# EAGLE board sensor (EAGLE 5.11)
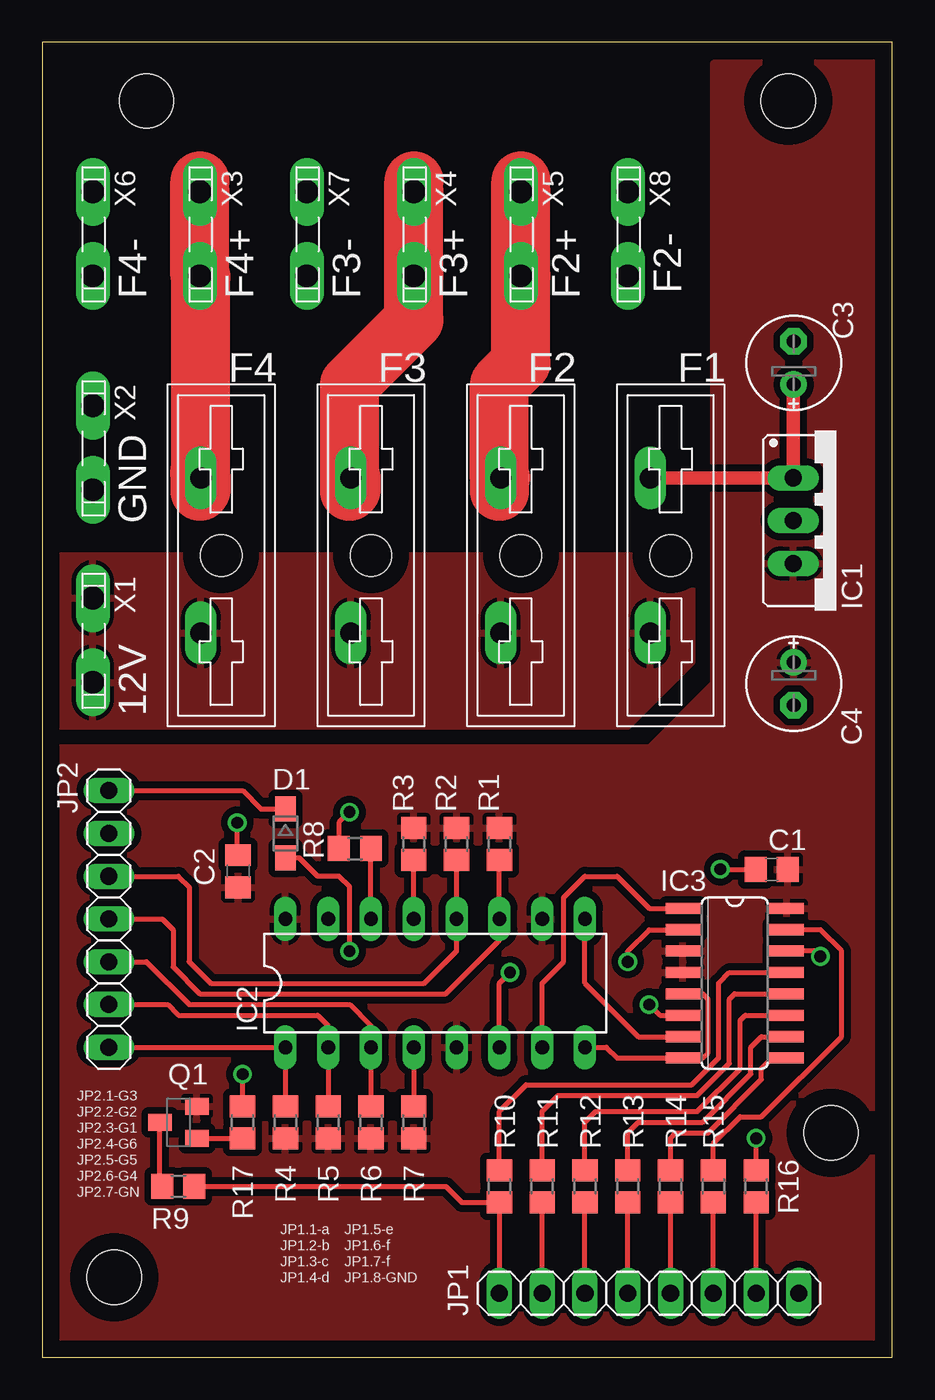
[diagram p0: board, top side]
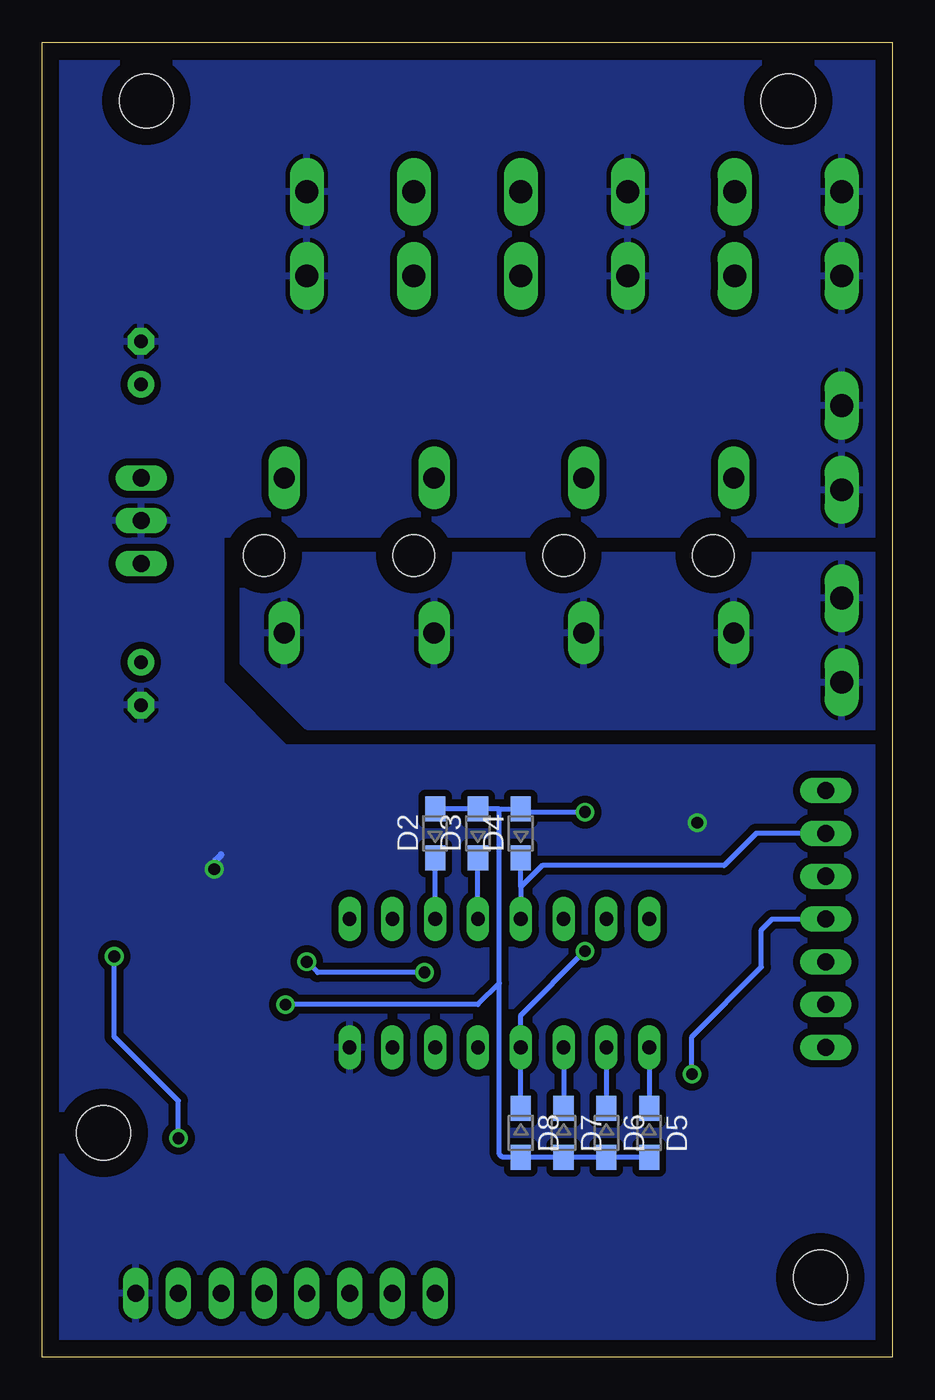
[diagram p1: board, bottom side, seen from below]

Size 50.47 x 78.09 mm. Coordinates in mm from the lower left corner, seen from the top.
Outline: 0,0 50.47,0 50.47,78.09 0,78.09 0,0
Copper layers (1*16): Top 0.035mm / dielectric 1.5mm / Bottom 0.035mm
Design rules "Bilex DRU": minimum track width 10mil, minimum drill 24mil, track to track 10mil, track to pad 10mil, pad to pad 10mil, via to via 10mil, smd to smd 10mil, copper to edge 40mil, drill to drill 8mil, minimum pad ring 10mil, minimum via ring 8mil, stop-mask expansion 4mil, vias tented up to drill 0mil, thermal gap 10mil
Holes 3.2 mm at 6.18,74.61 44.29,74.61 4.28,4.76 46.83,13.33

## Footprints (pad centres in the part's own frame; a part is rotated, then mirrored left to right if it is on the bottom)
C0805 = smd 1.3 x 1.5: 1 -0.95,0; 2 0.95,0
E2,5-6E = drill 0.813 pad 1.575 round: + -1.27,0 | drill 0.813 pad 1.575 octagon: - 1.27,0
SOD323-W = smd 1.5 x 1.2: A 1.45,0; C -1.45,0
FKS-HALTER = drill 1.25 long: P$1 -4.6,1.2; P$2 4.6,1.2 | hole 2.45: 0,0
78XXS = drill 1.016 long: GND 0,-2.54; IN -2.54,-2.54; OUT 2.54,-2.54
DIL16 = drill 0.813 long: 1 -8.89,-3.81; 2 -6.35,-3.81; 3 -3.81,-3.81; 4 -1.27,-3.81; 5 1.27,-3.81; 6 3.81,-3.81; 7 6.35,-3.81; 8 8.89,-3.81; 9 8.89,3.81; 10 6.35,3.81; 11 3.81,3.81; 12 1.27,3.81; 13 -1.27,3.81; 14 -3.81,3.81; 15 -6.35,3.81; 16 -8.89,3.81
SO16 = smd 0.66 x 2.032: 1 -4.445,-3.073; 2 -3.175,-3.073; 3 -1.905,-3.073; 4 -0.635,-3.073; 5 0.635,-3.073; 6 1.905,-3.073; 7 3.175,-3.073; 8 4.445,-3.073; 9 4.445,3.073; 10 3.175,3.073; 11 1.905,3.073; 12 0.635,3.073; 13 -0.635,3.073; 14 -1.905,3.073; 15 -3.175,3.073; 16 -4.445,3.073
1X08 = drill 1.016 long: 1 -8.89,0; 2 -6.35,0; 3 -3.81,0; 4 -1.27,0; 5 1.27,0; 6 3.81,0; 7 6.35,0; 8 8.89,0
1X07 = drill 1.016 long: 1 -7.62,0; 2 -5.08,0; 3 -2.54,0; 4 0,0; 5 2.54,0; 6 5.08,0; 7 7.62,0
SOT23-BEC = smd 1 x 1.4: B -0.95,-1.1; C 0,1.1; E 0.95,-1.1
R0805 = smd 1.3 x 1.5: 1 -0.95,0; 2 0.95,0
FS6,3 = drill 1.35 long: P1 -2.54,0; P2 2.46,0

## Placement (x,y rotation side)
C1  100n  [C0805]  43.3,28.98 180 top
C2  100n  [C0805]  11.63,28.87 90 top
C3  100u  [E2,5-6E]  44.61,59.05 90 top
C4  100u  [E2,5-6E]  44.61,40 270 top
D1  1N4148  [SOD323-W]  14.44,31.11 270 top
D2  1N4148  [SOD323-W]  27.14,31.11 90 bottom
D3  1N4148  [SOD323-W]  24.6,31.11 90 bottom
D4  1N4148  [SOD323-W]  22.06,31.11 90 bottom
D5  1N4148  [SOD323-W]  14.44,13.33 270 bottom
D6  1N4148  [SOD323-W]  16.98,13.33 270 bottom
D7  1N4148  [SOD323-W]  19.52,13.33 270 bottom
D8  1N4148  [SOD323-W]  22.06,13.33 270 bottom
F1  FKS-HALTER  [FKS-HALTER]  37.3,47.62 90 top
F2  FKS-HALTER  [FKS-HALTER]  28.41,47.62 90 top
F3  FKS-HALTER  [FKS-HALTER]  19.52,47.62 90 top
F4  FKS-HALTER  [FKS-HALTER]  10.63,47.62 90 top
IC1  7805  [78XXS]  47.12,49.68 270 top
IC2  74HC147N  [DIL16]  23.33,22.22 0 top
IC3  4511D  [SO16]  41.11,22.22 270 top
JP1  [1X08]  36.03,3.81 0 top
JP2  [1X07]  3.96,26.03 90 top
Q1  BC856ASMD  [SOT23-BEC]  8.09,13.96 90 top
R1  [R0805]  27.14,30.48 90 top
R2  [R0805]  24.6,30.48 90 top
R3  [R0805]  22.06,30.48 90 top
R4  [R0805]  14.44,13.96 270 top
R5  [R0805]  16.98,13.96 270 top
R6  [R0805]  19.52,13.96 270 top
R7  [R0805]  22.06,13.96 270 top
R8  [R0805]  18.57,30.21 0 top
R9  [R0805]  8.09,10.15 180 top
R10  [R0805]  27.14,10.15 90 top
R11  [R0805]  29.68,10.15 90 top
R12  [R0805]  32.22,10.15 90 top
R13  [R0805]  34.76,10.15 90 top
R14  [R0805]  37.3,10.15 90 top
R15  [R0805]  39.84,10.15 90 top
R16  [R0805]  42.38,10.15 90 top
R17  220  [R0805]  11.9,13.96 90 top
X1  [FS6,3]  3.01,42.54 270 top
X2  [FS6,3]  3.01,53.97 270 top
X3  [FS6,3]  9.36,66.67 270 top
X4  [FS6,3]  22.06,66.67 270 top
X5  [FS6,3]  28.41,66.67 270 top
X6  F4.N  [FS6,3]  3.01,66.67 270 top
X7  [FS6,3]  15.71,66.67 270 top
X8  [FS6,3]  34.76,66.67 270 top

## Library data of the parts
C1-C4 R1-R17 = rcl
D1-D8 = diode-1
F1-F4 = FKS-Halter
IC1 = v-reg
IC2 = 74xx-eu
IC3 = 45xx
JP1 JP2 = pinhead
Q1 = transistor-pnp
X1-X8 = Flachstecker

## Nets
+5V: C1.1 C2.1 C4.+ IC1.OUT IC2.5 IC2.10 IC2.16 IC3.3 IC3.4 IC3.16 Q1.E R1.2 R2.2 R3.2 R4.2 R5.2 R6.2 R7.2
+12V: F1.P$1 F2.P$1 F3.P$1 F4.P$1 X1.P1 X1.P2
GND: C1.2 C2.2 C3.- C4.- IC1.GND IC2.8 IC3.5 IC3.8 JP1.8 X2.P1 X2.P2 X6.P1 X6.P2 X7.P1 X7.P2 X8.P1 X8.P2
N$1: D1.C JP2.7
N$2: D3.C IC2.12 JP2.5 R2.1
N$3: C3.+ F1.P$2 IC1.IN
N$4: D2.C IC2.11 JP2.4 R1.1 R17.2
N$5: D4.C IC2.13 JP2.6 R3.1
N$6: D5.C IC2.1 JP2.1 R4.1
N$7: D6.C IC2.2 JP2.2 R5.1
N$8: D7.C IC2.3 JP2.3 R6.1
N$9: D1.A D8.C IC2.4 R7.1
N$10: Q1.C R9.2
N$11: F2.P$2 X5.P1 X5.P2
N$12: IC2.9 IC3.7
N$13: IC2.7 IC3.1
N$14: IC2.6 IC3.2
N$15: IC2.14 R8.2
N$16: D2.A D3.A D4.A D5.A D6.A D7.A D8.A IC3.6 R8.1
N$17: JP1.1 R9.1 R10.1
N$18: Q1.B R17.1
N$19: IC3.13 R10.2
N$20: IC3.14 R16.2
N$21: IC3.15 R15.2
N$22: IC3.9 R14.2
N$23: IC3.10 R13.2
N$24: IC3.11 R12.2
N$25: IC3.12 R11.2
N$26: JP1.2 R11.1
N$27: JP1.3 R12.1
N$28: JP1.4 R13.1
N$29: JP1.5 R14.1
N$30: JP1.6 R15.1
N$31: JP1.7 R16.1
N$32: F3.P$2 X4.P1 X4.P2
N$33: F4.P$2 X3.P1 X3.P2

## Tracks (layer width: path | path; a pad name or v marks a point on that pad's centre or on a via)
+5V
  pour Top (isolate 0.406): 0.47,36.19 0.47,0.63 50,0.63 50,76.83 39.84,76.83 39.84,40 36.03,36.19
+12V
  pour Bottom (isolate 0.406): 0.47,47.62 38.57,47.62 38.57,41.27 34.76,37.46 0.47,37.46
  pour Top (isolate 0.406): 0.47,47.62 38.57,47.62 38.57,41.27 34.76,37.46 0.47,37.46
GND  (via drill 0.7)
  Top 0.305: v40.26,28.98 C1.2 | IC2.8 33.49,18.41 34.12,17.78 IC3.8 39.2,17.78 39.52,18.09 39.52,21.27 39.2,21.59 IC3.5 | v11.58,31.75 11.58,29.87 C2.2
  Top 0.406: v40.25,28.98 v40.26,28.98
  Bottom 0.406: 40.17,29.51 39.84,29.84
  pour Bottom (isolate 0.406): 0.47,76.83 50,76.83 50,0.63 0.47,0.63 0.47,36.19 36.03,36.19 39.84,40 39.84,48.89 0.47,48.89
N$1
  Top 0.305: D1.C 12.99,32.56 11.9,33.65 JP2.7
N$2
  Top 0.305: R2.1 IC2.12 24.6,24.12 22.7,22.22 10,22.22 8.73,23.49 8.73,27.94 8.09,28.57 JP2.5
  Bottom 0.305: IC2.12 D3.C
N$3
  Top 0.813: F1.P$2 IC1.IN 44.58,57.75 C3.+
N$4  (via drill 0.7)
  Top 0.305: R1.1 IC2.11 27.14,24.76 23.96,21.59 9.36,21.59 7.77,23.17 7.77,25.39 7.14,26.03 JP2.4 | R17.2 v11.9,16.82
  Bottom 0.305: IC2.11 D2.C | v11.9,16.82 11.9,19.05 7.77,23.17 7.77,25.39 7.14,26.03 JP2.4
N$5
  Top 0.305: IC2.13 R3.1
  Bottom 0.305: 22.06,27.94 IC2.13 | 22.06,27.94 D4.C | JP2.6 8.09,31.11 10,29.21 20.79,29.21 22.06,27.94
N$6
  Top 0.305: R4.1 IC2.1 JP2.1
  Bottom 0.305: IC2.1 D5.C
N$7
  Top 0.305: R5.1 IC2.2 16.98,19.68 16.35,20.32 8.09,20.32 7.46,20.95 JP2.2
  Bottom 0.305: IC2.2 D6.C
N$8
  Top 0.305: R6.1 IC2.3 19.52,19.68 18.25,20.95 8.73,20.95 6.18,23.49 JP2.3
  Bottom 0.305: IC2.3 D7.C
N$9  (via drill 0.7)
  Top 0.305: IC2.4 R7.1 | D1.A 15.26,29.66 16.35,28.57 17.62,28.57 18.25,27.94 v18.25,24.12
  Bottom 0.305: D8.C IC2.4 22.06,20.32 v18.25,24.12
N$10
  Top 0.305: Q1.C 6.99,10.3 R9.2
N$11
  Top 3.5: 28.41,69.84 X5.P1 X5.P2 28.41,59.05 27.14,57.78 27.14,52.15 | 27.14,52.15 27.14,51.43 | F2.P$2 27.14,52.15
N$12
  Top 0.305: IC3.7 35.4,19.05 32.22,22.22 IC2.9
N$13
  Top 0.305: IC2.7 29.68,22.22 30.95,23.49 30.95,27.3 32.22,28.57 34.12,28.57 36.03,26.67 IC3.1
N$14  (via drill 0.7)
  Top 0.305: IC2.6 27.14,22.22 v27.78,22.86 | v34.76,23.49 34.76,24.12 36.03,25.39 IC3.2
  Bottom 0.305: v27.78,22.86 34.12,22.86 v34.76,23.49
N$15
  Top 0.305: R8.2 IC2.14
N$16  (via drill 0.7)
  Top 0.305: R8.1 17.62,31.75 v18.25,32.38 | IC3.6 36.66,20.32 v36.03,20.95
  Bottom 0.305: D5.A D6.A D7.A D8.A 23.15,11.88 23.33,12.06 23.33,22.22 | D2.A D3.A 23.33,32.56 | 23.33,32.56 D4.A | 23.33,22.22 23.33,32.56 | 21.88,32.38 v18.25,32.38 | v36.03,20.95 24.6,20.95 23.33,22.22
  Bottom 0.406: D4.A 21.88,32.38
N$17
  Top 0.305: JP1.1 R10.1 24.92,9.2 23.96,10.15 R9.1
N$18
  Top 0.305: Q1.B R17.1
N$19
  Top 0.305: IC3.13 40.79,22.86 40.16,22.22 40.16,17.78 38.57,16.19 28.73,16.19 27.14,14.6 R10.2
N$20  (via drill 0.7)
  Top 0.305: IC3.14 45.87,24.12 v46.19,23.81 | R16.2 v42.38,13.01
  Bottom 0.305: v46.19,23.81 46.19,19.05 42.38,15.23 v42.38,13.01
N$21
  Top 0.305: IC3.15 46.19,25.39 47.46,24.12 47.46,19.05 42.7,14.28 41.43,14.28 39.84,12.69 R15.2
N$22
  Top 0.305: IC3.9 43.33,17.78 42.7,17.14 42.7,16.51 39.52,13.33 37.62,13.33 37.3,13.01 R14.2
N$23
  Top 0.305: IC3.10 42.7,19.05 42.06,18.41 42.06,16.82 39.2,13.96 35.4,13.96 34.76,13.33 R13.2
N$24
  Top 0.305: IC3.11 41.74,20.32 41.43,20 41.43,17.14 38.89,14.6 32.86,14.6 32.22,13.96 R12.2
N$25
  Top 0.305: IC3.12 41.11,21.59 40.79,21.27 40.79,17.46 38.89,15.55 30.63,15.55 29.68,14.6 R11.2
N$26
  Top 0.305: JP1.2 R11.1
N$27
  Top 0.305: JP1.3 R12.1
N$28
  Top 0.305: JP1.4 R13.1
N$29
  Top 0.305: JP1.5 R14.1
N$30
  Top 0.305: JP1.6 R15.1
N$31
  Top 0.305: JP1.7 R16.1
N$32
  Top 3.5: 22.06,69.84 X4.P1 X4.P2 22.06,61.59 18.25,57.78 18.25,51.43 18.32,51.5 F3.P$2
N$33
  Top 3.5: 9.36,69.84 X3.P1 X3.P2 9.43,64.14 F4.P$2 | F4.P$2 9.43,51.5 9.36,51.43 9.36,52.29 | 9.36,52.29 9.36,52.7 | F4.P$2 9.36,52.29

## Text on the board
tOrigins: GSF-GPEv1.0 | S.Plaschke 2011
tNames: F4- | F4+ | F3- | F3+ | F2+ | F2- | GND | 12V | JP2.1-G3 | JP2.2-G2 | JP2.3-G1 | JP2.4-G6 | JP2.5-G5 | JP2.6-G4 | JP2.7-GN | JP1.1-a | JP1.5-e | JP1.2-b | JP1.6-f | JP1.3-c | JP1.7-f | JP1.4-d | JP1.8-GND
